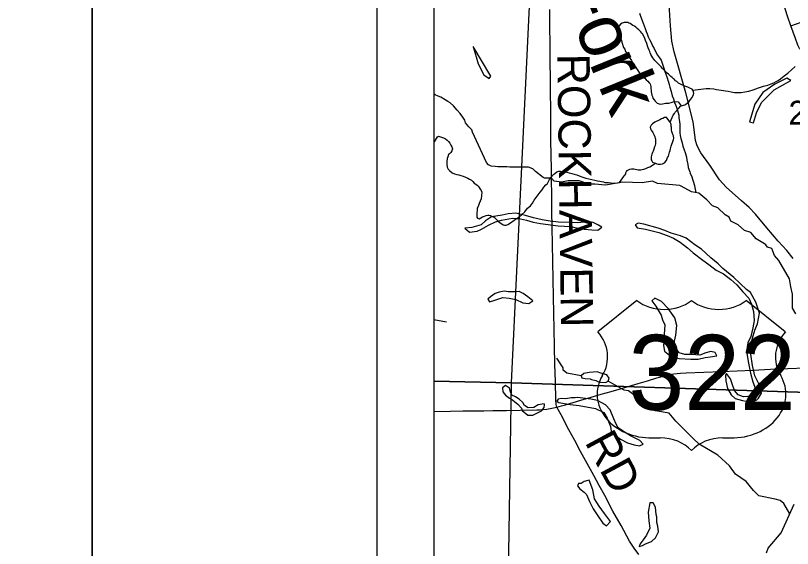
# Model space of a CAD drawing. Extents: x -6.1 to 38, y -7.7 to 22.
# Drawn here: x 1.365 to 2.73, y 15.778 to 16.715 of the extents above; entities that cross this region are included whole.
import ezdxf

# ---------------------------------------------------------------- set-up
doc = ezdxf.new("R2010")
doc.units = 0
for name, color, linetype in [('GM_X_Corporation', 7, 'Continuous'), ('GM_X_Minor_Lake', 7, 'Continuous'), ('GM_X_Minor_River', 7, 'Continuous'), ('GM_X_Minor_River_Text', 7, 'Continuous'), ('GM_X_Section_Text', 7, 'Continuous'), ('GM_X_Township_Road', 7, 'Continuous'), ('GM_X_Township_Road_Text', 7, 'Continuous'), ('GM_X_US_Location', 7, 'Continuous'), ('GM_X_US_Route', 7, 'Continuous'), ('GM_X_US_Shield', 7, 'Continuous'), ('SH_Border', 7, 'Continuous'), ('SH_Data', 7, 'Continuous')]:
    doc.layers.add(name, color=color, linetype=linetype)

msp = doc.modelspace()

# ---------------------------------------------------------------- linework, layer by layer
at = {"layer": 'GM_X_Corporation'}
for points in [[(2.1, 20.0941), (2.1, 15.0637), (2.2727, 15.0594), (2.8416, 15.0475)], [(2.1, 19.3655), (2.1, 14.5232), (2.6997, 14.5255), (2.9953, 14.5306)]]:
    msp.add_lwpolyline(points, dxfattribs=at)
for points in [[(2.1, 17.0798), (2.1, 16.0722), (2.2364, 16.0695), (2.2848, 17.0751)], [(2.2848, 17.0751), (3.2573, 17.0475), (3.2572, 17.0301), (3.2483, 16.4521), (3.2427, 16.0367), (2.2364, 16.0695)], [(2.1, 16.0722), (2.1, 15.064), (2.1873, 15.0619), (2.2211, 15.061), (2.2364, 16.0695)], [(2.2364, 16.0695), (3.2427, 16.0367), (3.2407, 15.9466), (3.2349, 15.609), (3.2294, 15.3062), (3.225, 15.0392), (2.2211, 15.061)]]:
    msp.add_lwpolyline(points, close=True, dxfattribs=at)
at = {"layer": 'GM_X_Minor_Lake'}
for p, q in [((2.3801, 16.3513), (2.3643, 16.3518)), ((2.4943, 16.3415), (2.4694, 16.3484)), ((2.2452, 16.2293), (2.235, 16.2293)), ((2.4902, 16.2039), (2.4962, 16.1944)), ((2.3774, 16.075), (2.3849, 16.0733)), ((2.3759, 16.0404), (2.3528, 16.0435)), ((2.2424, 16.0359), (2.2477, 16.0321)), ((2.3642, 15.896), (2.3592, 15.8926)), ((2.4921, 15.8237), (2.4918, 15.8337))]:
    msp.add_line(p, q, dxfattribs=at)
for points in [[(2.5126, 16.6118), (2.5103, 16.6141), (2.5076, 16.6163), (2.5049, 16.619), (2.5018, 16.6223), (2.4999, 16.625), (2.4968, 16.628), (2.4949, 16.6299), (2.4888, 16.6363), (2.4868, 16.6385), (2.4849, 16.6408), (2.483, 16.6438), (2.4818, 16.6469), (2.4806, 16.6495), (2.4798, 16.6518), (2.4783, 16.6544), (2.4771, 16.6582), (2.4759, 16.6616), (2.4743, 16.6662), (2.4724, 16.6711), (2.4708, 16.6756), (2.4689, 16.6794), (2.4673, 16.6821), (2.4658, 16.6843), (2.4642, 16.6862), (2.4623, 16.6881), (2.4604, 16.69), (2.4573, 16.6922), (2.455, 16.6945), (2.4527, 16.6964), (2.45, 16.6979), (2.4477, 16.6994), (2.4454, 16.7009), (2.4431, 16.702), (2.4412, 16.7027), (2.4393, 16.7031), (2.4367, 16.7031), (2.4348, 16.703), (2.4314, 16.7019), (2.4283, 16.6999), (2.4261, 16.6973), (2.425, 16.6953), (2.425, 16.6923), (2.425, 16.6896), (2.4258, 16.6855), (2.4263, 16.6828), (2.427, 16.6805), (2.4274, 16.6783), (2.4282, 16.676), (2.429, 16.6741), (2.4298, 16.6711), (2.4306, 16.6684), (2.4337, 16.6589), (2.4357, 16.6559), (2.4369, 16.6521), (2.4388, 16.6495), (2.4407, 16.6461), (2.4427, 16.643), (2.4446, 16.6404), (2.4462, 16.6378), (2.4473, 16.6359), (2.4485, 16.6332), (2.4497, 16.6313), (2.4508, 16.6294), (2.4524, 16.6276), (2.4551, 16.6238), (2.4574, 16.62), (2.4597, 16.6166), (2.4616, 16.6136), (2.4632, 16.6113), (2.4655, 16.6094), (2.4682, 16.6076), (2.4709, 16.6049), (2.4736, 16.6023), (2.4763, 16.5997), (2.4786, 16.597), (2.4801, 16.5948), (2.4813, 16.5906), (2.4813, 16.5887), (2.4817, 16.586), (2.4821, 16.5837), (2.4822, 16.5811), (2.4826, 16.578), (2.483, 16.5754), (2.4842, 16.5727), (2.4853, 16.5701), (2.4873, 16.5667), (2.4892, 16.5644), (2.4927, 16.561), (2.4961, 16.5599), (2.4984, 16.5596), (2.5018, 16.56), (2.5048, 16.5604), (2.5075, 16.5608), (2.5094, 16.5608), (2.5132, 16.5612), (2.517, 16.562), (2.5208, 16.5632), (2.5268, 16.564), (2.5295, 16.5633), (2.5349, 16.5561)], [(2.1691, 16.6607), (2.1784, 16.6304), (2.1883, 16.6111), (2.1977, 16.6047), (2.2004, 16.6085)], [(2.2004, 16.6085), (2.1691, 16.6607)], [(2.5349, 16.5561), (2.5414, 16.5581), (2.5432, 16.5593), (2.5451, 16.5612), (2.5481, 16.5635), (2.5515, 16.5673), (2.5541, 16.5712), (2.5556, 16.5738), (2.5567, 16.5757), (2.5571, 16.578), (2.5567, 16.5811), (2.5555, 16.5837), (2.554, 16.5856), (2.5513, 16.5871), (2.549, 16.5882), (2.5467, 16.589), (2.5448, 16.5897), (2.5429, 16.5904), (2.541, 16.5912), (2.5391, 16.5919), (2.5372, 16.5927), (2.5337, 16.5945), (2.5303, 16.5964), (2.5272, 16.599), (2.5249, 16.6001), (2.523, 16.6024), (2.5211, 16.6039), (2.5191, 16.6062), (2.5168, 16.608), (2.5149, 16.6099), (2.5126, 16.6118)], [(2.7206, 16.6053), (2.6992, 16.5943), (2.6781, 16.5798), (2.6642, 16.5596), (2.6549, 16.5285), (2.6621, 16.5267)], [(2.6621, 16.5267), (2.6669, 16.5441), (2.6759, 16.5623), (2.6981, 16.5844), (2.7278, 16.6012), (2.7206, 16.6053)], [(2.5097, 16.5357), (2.5055, 16.5357), (2.5025, 16.5341), (2.5002, 16.5334), (2.4976, 16.5318), (2.4949, 16.5303), (2.4911, 16.5287), (2.4885, 16.5275), (2.4843, 16.5248), (2.4821, 16.5225), (2.4806, 16.5187), (2.481, 16.5157), (2.4822, 16.5134), (2.4837, 16.5115), (2.4849, 16.5093), (2.4861, 16.5074), (2.4876, 16.5047), (2.4888, 16.5021), (2.4892, 16.4998), (2.49, 16.4979), (2.49, 16.4956), (2.49, 16.493), (2.4897, 16.4899), (2.489, 16.4869), (2.4879, 16.4842), (2.4868, 16.4804), (2.4857, 16.4766), (2.4842, 16.4743), (2.4831, 16.4712), (2.4827, 16.4689), (2.482, 16.4666), (2.482, 16.4632), (2.482, 16.4613), (2.4832, 16.4594), (2.4844, 16.4575), (2.4874, 16.4561), (2.4897, 16.4553), (2.492, 16.4542), (2.4943, 16.4538), (2.4966, 16.4539), (2.4985, 16.4539), (2.5019, 16.4543), (2.5053, 16.4562), (2.509, 16.4604), (2.5109, 16.4654), (2.5124, 16.4681), (2.5138, 16.4723), (2.5146, 16.475), (2.5153, 16.4776), (2.516, 16.4807), (2.5168, 16.4833), (2.5175, 16.4852), (2.5186, 16.4887), (2.5193, 16.4917), (2.5208, 16.4952), (2.5215, 16.4971), (2.5219, 16.4997), (2.5211, 16.5035), (2.5203, 16.5058), (2.5191, 16.5092), (2.5183, 16.5115), (2.5179, 16.5138), (2.5179, 16.5164), (2.5179, 16.5183), (2.5175, 16.5202), (2.5171, 16.5236), (2.5166, 16.5255), (2.5155, 16.5274), (2.5099, 16.5354)], [(2.5099, 16.5354), (2.5097, 16.5357)], [(2.3643, 16.3518), (2.3533, 16.3507), (2.3378, 16.3515), (2.3193, 16.3519), (2.3049, 16.3535), (2.2905, 16.3562), (2.2754, 16.3593), (2.2614, 16.3638), (2.2444, 16.3677), (2.2308, 16.3662), (2.2202, 16.364), (2.2013, 16.361), (2.1911, 16.3542), (2.1831, 16.3474), (2.1669, 16.3425), (2.1544, 16.3414), (2.1631, 16.3342), (2.1763, 16.336), (2.1839, 16.3394), (2.196, 16.3466), (2.2085, 16.3526), (2.2191, 16.3556), (2.2387, 16.3586), (2.2527, 16.3578), (2.2629, 16.3551), (2.275, 16.3517), (2.2875, 16.3494), (2.3185, 16.3451), (2.3412, 16.3443), (2.3582, 16.34), (2.3778, 16.3385), (2.3881, 16.3377), (2.3952, 16.343), (2.3896, 16.3468), (2.3801, 16.3513)], [(2.4694, 16.3484), (2.4592, 16.35), (2.4542, 16.3473), (2.4573, 16.342), (2.4724, 16.3397), (2.4954, 16.3339), (2.5102, 16.3282), (2.5211, 16.3236), (2.5328, 16.3168), (2.546, 16.3069), (2.5558, 16.2981), (2.5728, 16.2852), (2.5834, 16.2772), (2.5966, 16.2676), (2.6094, 16.2612), (2.6219, 16.2509), (2.6324, 16.2414), (2.6434, 16.2296), (2.6536, 16.2182), (2.6584, 16.2075), (2.6622, 16.1946), (2.6633, 16.1787), (2.661, 16.1658), (2.6572, 16.1507), (2.6522, 16.1397), (2.6495, 16.1245), (2.6529, 16.1037), (2.6566, 16.0866), (2.6607, 16.0714), (2.6652, 16.0589), (2.6644, 16.0498), (2.6595, 16.046), (2.6444, 16.0445), (2.6349, 16.0484), (2.6285, 16.0556), (2.6244, 16.0674), (2.6214, 16.0765), (2.6143, 16.086), (2.6127, 16.0829), (2.6131, 16.0731), (2.6161, 16.0594), (2.6225, 16.048), (2.6296, 16.0419), (2.6425, 16.0381), (2.6493, 16.037), (2.6606, 16.0362), (2.6678, 16.0395), (2.6705, 16.0422), (2.6762, 16.0513), (2.6743, 16.0615), (2.6645, 16.0816), (2.66, 16.0999), (2.6571, 16.12), (2.6575, 16.1344), (2.6602, 16.1476), (2.664, 16.162), (2.6689, 16.173), (2.6724, 16.192), (2.666, 16.2113), (2.6566, 16.2284), (2.6494, 16.2334), (2.6272, 16.2547), (2.6083, 16.2706), (2.6, 16.2786), (2.5868, 16.2893), (2.5706, 16.3041), (2.5589, 16.3121), (2.5438, 16.3235), (2.5336, 16.3281), (2.517, 16.3323), (2.506, 16.3369), (2.4943, 16.3415)], [(2.235, 16.2293), (2.2308, 16.2293), (2.224, 16.2305), (2.2153, 16.2286), (2.2078, 16.2264), (2.1998, 16.2207), (2.1949, 16.2162), (2.1983, 16.212), (2.2074, 16.2146), (2.2214, 16.2191), (2.2323, 16.2183), (2.2444, 16.2156), (2.2565, 16.2103), (2.2671, 16.2087), (2.2739, 16.2137), (2.2656, 16.2205), (2.2569, 16.2262), (2.2501, 16.2297), (2.2452, 16.2293)], [(2.4962, 16.1944), (2.4996, 16.1883), (2.5022, 16.1803), (2.506, 16.1712), (2.5052, 16.1542), (2.5051, 16.1447), (2.5036, 16.1348), (2.5058, 16.125), (2.5175, 16.1158), (2.5311, 16.1124), (2.5516, 16.1108), (2.5648, 16.1108), (2.5769, 16.1138), (2.5856, 16.1149), (2.5973, 16.1167), (2.5943, 16.1228), (2.5871, 16.1243), (2.5781, 16.1221), (2.5678, 16.118), (2.5538, 16.1191), (2.5414, 16.1192), (2.5312, 16.1219), (2.5244, 16.1321), (2.5229, 16.1427), (2.5256, 16.153), (2.5271, 16.17), (2.5234, 16.1837), (2.5117, 16.2), (2.5, 16.2122), (2.4887, 16.2183), (2.483, 16.2138), (2.4902, 16.2039)], [(2.3849, 16.0733), (2.3881, 16.0719), (2.393, 16.0703), (2.4017, 16.0699), (2.4066, 16.0722), (2.4081, 16.0775), (2.4044, 16.0836), (2.3938, 16.0866), (2.3874, 16.0889), (2.3734, 16.0875), (2.3639, 16.0856), (2.359, 16.0818), (2.3605, 16.0784), (2.3662, 16.0772), (2.3749, 16.0761), (2.3774, 16.075)], [(2.2477, 16.0321), (2.2541, 16.0249), (2.2552, 16.0207), (2.2654, 16.0127), (2.2741, 16.0127), (2.2813, 16.0161), (2.2893, 16.0202), (2.2942, 16.0259), (2.2946, 16.0305), (2.2942, 16.0327), (2.2836, 16.0309), (2.2757, 16.026), (2.2662, 16.0256), (2.2598, 16.0294), (2.2564, 16.0347), (2.25, 16.0408), (2.2436, 16.0446), (2.2375, 16.0477), (2.2349, 16.0538), (2.2334, 16.0598), (2.2262, 16.0648), (2.2209, 16.0606), (2.2213, 16.0534), (2.2262, 16.0477), (2.2334, 16.0424), (2.2383, 16.0397), (2.2424, 16.0359)], [(2.3528, 16.0435), (2.3483, 16.0432), (2.3415, 16.0432), (2.332, 16.041), (2.3241, 16.0417), (2.3184, 16.0406), (2.3162, 16.0372), (2.3196, 16.0345), (2.3396, 16.0315), (2.3555, 16.0295), (2.3842, 16.0245), (2.3989, 16.0169), (2.4049, 16.0074), (2.4109, 15.9926), (2.4117, 15.9846), (2.417, 15.9785), (2.4283, 15.9701), (2.4407, 15.9637), (2.4521, 15.9602), (2.4615, 15.9583), (2.468, 15.9617), (2.4623, 15.9681), (2.4457, 15.9761), (2.4366, 15.9819), (2.4242, 15.9902), (2.4208, 15.9967), (2.4163, 16.0058), (2.4099, 16.0218), (2.402, 16.0309), (2.388, 16.0381), (2.3759, 16.0404)], [(2.3592, 15.8926), (2.3543, 15.8926), (2.3524, 15.8885), (2.357, 15.8828), (2.3641, 15.8774), (2.3687, 15.8733), (2.3739, 15.8607), (2.3803, 15.8478), (2.3882, 15.8357), (2.3969, 15.8227), (2.4037, 15.8182), (2.4109, 15.8257), (2.3999, 15.8398), (2.3909, 15.8527), (2.3826, 15.8652), (2.3796, 15.8812), (2.3729, 15.8983), (2.3706, 15.8979), (2.3642, 15.896)], [(2.4918, 15.8337), (2.4911, 15.8376), (2.49, 15.8505), (2.4855, 15.8581), (2.4798, 15.8585), (2.4767, 15.8422), (2.4778, 15.8267), (2.4797, 15.8138), (2.474, 15.8016), (2.4679, 15.7933), (2.4626, 15.7861), (2.461, 15.7816), (2.4667, 15.7831), (2.4724, 15.7861), (2.4826, 15.7902), (2.4898, 15.797), (2.4948, 15.8073), (2.494, 15.8171), (2.4921, 15.8237)]]:
    msp.add_lwpolyline(points, dxfattribs=at)
at = {"layer": 'GM_X_Minor_River'}
for points in [[(2.4617, 16.7191), (2.4636, 16.7138), (2.4663, 16.7066), (2.4682, 16.7017), (2.4697, 16.6968), (2.4716, 16.6922), (2.4731, 16.6869), (2.4751, 16.6828), (2.477, 16.6775), (2.4793, 16.6729), (2.4819, 16.668), (2.4846, 16.662), (2.4873, 16.6571), (2.4911, 16.6495), (2.493, 16.6453), (2.4968, 16.6408), (2.4998, 16.6366), (2.5029, 16.626), (2.5052, 16.6207), (2.506, 16.6166), (2.5098, 16.6071), (2.5125, 16.598), (2.514, 16.5939), (2.5148, 16.5893), (2.5171, 16.5818), (2.519, 16.5742), (2.5213, 16.5685), (2.5232, 16.5625), (2.5255, 16.5572), (2.5271, 16.5522), (2.5305, 16.5397), (2.5309, 16.5356), (2.5321, 16.5284), (2.5325, 16.5242), (2.5325, 16.517), (2.5322, 16.5132), (2.5326, 16.5087), (2.5333, 16.5041), (2.5345, 16.4992), (2.5368, 16.4913), (2.538, 16.4852), (2.5399, 16.4792), (2.5418, 16.4742), (2.5433, 16.4701), (2.5441, 16.4659), (2.5449, 16.461), (2.5464, 16.453), (2.5472, 16.4481), (2.5499, 16.4405), (2.5507, 16.4377)], [(2.5555, 16.5837), (2.579, 16.5866), (2.5851, 16.5867), (2.5924, 16.586), (2.5969, 16.5849), (2.6011, 16.5846), (2.6053, 16.5842), (2.6091, 16.5835), (2.6129, 16.5828), (2.6175, 16.5821), (2.6228, 16.581), (2.6285, 16.5799), (2.64, 16.5796), (2.6464, 16.5808), (2.6536, 16.5824), (2.6616, 16.5848), (2.6706, 16.5879), (2.6797, 16.591), (2.6873, 16.593), (2.693, 16.595), (2.6975, 16.5969), (2.7017, 16.5989), (2.7055, 16.6008), (2.7096, 16.6039), (2.716, 16.6089), (2.722, 16.6139), (2.7284, 16.6197), (2.7352, 16.6254)], [(2.279, 16.4411), (2.2741, 16.4455), (2.2665, 16.4485), (2.251, 16.4484), (2.2469, 16.4488), (2.2404, 16.4484), (2.234, 16.4487), (2.2283, 16.4491), (2.2231, 16.4494), (2.2125, 16.4494), (2.2079, 16.4497), (2.2011, 16.4505), (2.1962, 16.4524), (2.1928, 16.4569), (2.168, 16.5102), (2.1668, 16.5144), (2.1619, 16.5193), (2.1558, 16.5265), (2.1547, 16.531), (2.1512, 16.5367), (2.1467, 16.5427), (2.141, 16.5488), (2.1349, 16.5563), (2.1288, 16.5616), (2.125, 16.5639), (2.1201, 16.5669), (2.1125, 16.5714), (2.1076, 16.5733), (2.1027, 16.5759), (2.1, 16.5772)], [(2.5155, 16.5274), (2.521, 16.54), (2.5229, 16.5427), (2.5244, 16.545), (2.5289, 16.5504), (2.5312, 16.5531), (2.5338, 16.5557), (2.5349, 16.5561)], [(2.1, 16.4932), (2.1011, 16.4929), (2.1064, 16.5017), (2.1086, 16.5028), (2.1121, 16.5021), (2.1174, 16.5003), (2.1208, 16.4984)], [(2.1208, 16.4984), (2.1239, 16.4962), (2.1262, 16.4935), (2.1285, 16.4905), (2.1301, 16.4871), (2.1316, 16.4844), (2.1324, 16.4826), (2.1328, 16.4807), (2.1321, 16.4772), (2.1299, 16.4742), (2.128, 16.4722), (2.1261, 16.4707), (2.1246, 16.4669), (2.1235, 16.4635), (2.1228, 16.4585), (2.1229, 16.4536), (2.1237, 16.4486), (2.1253, 16.4452), (2.128, 16.4426), (2.1326, 16.4388), (2.1368, 16.437), (2.1406, 16.4359), (2.1444, 16.4348), (2.1478, 16.4337), (2.1516, 16.4326), (2.1558, 16.4307), (2.1597, 16.4292), (2.1631, 16.4273), (2.1662, 16.4255), (2.1689, 16.4232), (2.1712, 16.4206), (2.1742, 16.4187), (2.1762, 16.4168), (2.1781, 16.415), (2.18, 16.4127), (2.1819, 16.41), (2.1835, 16.4074), (2.1847, 16.4048), (2.1833, 16.3926), (2.1818, 16.3888), (2.1799, 16.3846), (2.1788, 16.3811), (2.1774, 16.3784), (2.1766, 16.3762), (2.1763, 16.3731), (2.1756, 16.3685), (2.1756, 16.364), (2.176, 16.3606), (2.1772, 16.3587), (2.1799, 16.3576), (2.1855, 16.361), (2.1893, 16.3626), (2.1924, 16.3638), (2.195, 16.3642), (2.1973, 16.3642), (2.1996, 16.3635), (2.2026, 16.362), (2.2061, 16.3605), (2.2088, 16.3582), (2.2111, 16.356), (2.2134, 16.3537), (2.2168, 16.3507), (2.2195, 16.3488), (2.2222, 16.3473), (2.2245, 16.3466), (2.2271, 16.3466), (2.2302, 16.3478), (2.2351, 16.3509), (2.2415, 16.3551), (2.2483, 16.3598), (2.2543, 16.3648), (2.2599, 16.3698), (2.2648, 16.3763), (2.2701, 16.3805), (2.2735, 16.3855), (2.2768, 16.3905), (2.2798, 16.3951), (2.2836, 16.3997), (2.2873, 16.4043), (2.2903, 16.4085), (2.2937, 16.4131), (2.297, 16.4173), (2.2997, 16.4196), (2.3012, 16.4219), (2.3034, 16.4268), (2.306, 16.4303), (2.3113, 16.436), (2.3131, 16.4376), (2.3165, 16.4403), (2.3196, 16.4415), (2.3226, 16.4415), (2.326, 16.4411), (2.3298, 16.4404), (2.334, 16.4397), (2.3382, 16.4386), (2.3428, 16.4375), (2.347, 16.436), (2.3516, 16.4349), (2.3558, 16.4331), (2.3619, 16.4312), (2.3672, 16.4294)], [(2.3672, 16.4294), (2.3726, 16.4279), (2.3779, 16.4268), (2.3832, 16.4257), (2.3878, 16.4246), (2.392, 16.4239), (2.395, 16.4232), (2.3981, 16.4225), (2.4004, 16.4217), (2.4023, 16.4217), (2.4042, 16.4214), (2.4072, 16.4214), (2.411, 16.4211), (2.4152, 16.4207), (2.419, 16.4204), (2.4232, 16.4208), (2.4262, 16.4216), (2.4296, 16.4258), (2.4322, 16.4296), (2.4345, 16.4331), (2.4363, 16.435), (2.4375, 16.4369), (2.4378, 16.4388), (2.4389, 16.4407), (2.4401, 16.4427), (2.4423, 16.4438), (2.4446, 16.445), (2.4476, 16.4454), (2.4514, 16.4454), (2.4594, 16.444), (2.4613, 16.444), (2.464, 16.444), (2.4663, 16.4444), (2.4693, 16.4452), (2.4727, 16.4464), (2.4765, 16.448), (2.4799, 16.4491), (2.4897, 16.4553)], [(2.6459, 16.3369), (2.635, 16.3472), (2.6222, 16.3536), (2.6192, 16.3605), (2.6124, 16.365), (2.5995, 16.3772), (2.5897, 16.3803), (2.5799, 16.3909), (2.5659, 16.4027), (2.5531, 16.4054), (2.535, 16.4153), (2.5327, 16.4165), (2.4934, 16.42), (2.4847, 16.4238), (2.4662, 16.4208), (2.4321, 16.4221), (2.4019, 16.4169), (2.383, 16.4184), (2.3724, 16.4185), (2.3558, 16.4246), (2.3365, 16.4247), (2.3244, 16.4224), (2.3119, 16.424), (2.307, 16.4293), (2.2945, 16.429), (2.2923, 16.4301), (2.279, 16.4411)], [(2.561, 16.4038), (2.5588, 16.416), (2.5533, 16.433), (2.5507, 16.4377)], [(2.7363, 16.1906), (2.7303, 16.2005), (2.7307, 16.2252), (2.7273, 16.2381), (2.7251, 16.2521), (2.7067, 16.2844), (2.6988, 16.2935), (2.6943, 16.3053), (2.6863, 16.3079), (2.6833, 16.3121), (2.6814, 16.314), (2.6667, 16.3228), (2.6573, 16.3334), (2.6459, 16.3369)], [(2.359, 16.0818), (2.3341, 16.0861), (2.3273, 16.0918), (2.3273, 16.0959), (2.3164, 16.113)], [(2.7255, 15.8393), (2.7154, 15.857), (2.7089, 15.8624), (2.6999, 15.8647), (2.6712, 15.8704), (2.6621, 15.8799), (2.6493, 15.8959), (2.6304, 15.9085), (2.6199, 15.9233), (2.5991, 15.9423), (2.5667, 15.9614), (2.5557, 15.9716), (2.5255, 16.0021), (2.5135, 16.0161), (2.49, 16.0204), (2.487, 16.0215), (2.4742, 16.0254), (2.4538, 16.0463), (2.4425, 16.0554), (2.4346, 16.0566), (2.4191, 16.065), (2.4066, 16.0722)], [(2.6845, 15.7707), (2.6875, 15.7786), (2.7103, 15.8055), (2.7331, 15.8562)]]:
    msp.add_lwpolyline(points, dxfattribs=at)
at = {"layer": 'GM_X_Township_Road'}
msp.add_line((2.1, 16.1805), (2.1226, 16.1768), dxfattribs=at)
for points in [[(2.7521, 16.6497), (2.7474, 16.6527), (2.7429, 16.6571), (2.7398, 16.6631), (2.7355, 16.6749), (2.7278, 16.6972), (2.7225, 16.7121), (2.7173, 16.727), (2.7121, 16.7422), (2.7068, 16.7573), (2.7036, 16.7679), (2.7025, 16.776), (2.702, 16.7801), (2.7019, 16.7897), (2.7016, 16.8119), (2.7013, 16.8342), (2.701, 16.8653), (2.7007, 16.891), (2.7004, 16.9167), (2.7001, 16.9444), (2.6997, 16.9721), (2.6997, 16.9822)], [(2.4604, 15.7675), (2.4525, 15.7789), (2.4442, 15.7912), (2.4294, 15.8184), (2.4147, 15.844), (2.4004, 15.871), (2.3908, 15.8886), (2.3812, 15.9063), (2.3697, 15.9274), (2.3582, 15.9485), (2.3478, 15.9677), (2.3374, 15.9869), (2.3238, 16.013), (2.3164, 16.0265), (2.3154, 16.031), (2.3145, 16.04), (2.3138, 16.071), (2.3131, 16.1021), (2.3124, 16.133), (2.3117, 16.1639), (2.3111, 16.1921), (2.3105, 16.2203), (2.3099, 16.2513), (2.3093, 16.2824), (2.3087, 16.3134), (2.3081, 16.3422), (2.3075, 16.3709), (2.3073, 16.402), (2.3071, 16.4236), (2.3069, 16.4451), (2.3065, 16.4704), (2.306, 16.4956), (2.3059, 16.524), (2.3058, 16.5523), (2.3055, 16.5778), (2.3051, 16.6033), (2.3048, 16.6343), (2.3046, 16.6654), (2.3043, 16.6956), (2.3041, 16.7258)], [(2.7318, 16.288), (2.7202, 16.3023), (2.7052, 16.3183), (2.6856, 16.3416), (2.6653, 16.366), (2.6543, 16.3774), (2.641, 16.3893), (2.6139, 16.4136), (2.6024, 16.4265), (2.5853, 16.4523), (2.5693, 16.474), (2.5628, 16.4861), (2.5601, 16.4955), (2.5579, 16.5145), (2.5558, 16.5284), (2.5431, 16.5792), (2.5223, 16.6516), (2.5182, 16.67), (2.5161, 16.6973), (2.5139, 16.7347)], [(2.7278, 16.6972), (2.7571, 16.7075)]]:
    msp.add_lwpolyline(points, dxfattribs=at)
at = {"layer": 'GM_X_US_Route'}
msp.add_lwpolyline([(2.1, 16.019), (2.1295, 16.0196), (2.1509, 16.02), (2.1722, 16.0203), (2.1881, 16.0204), (2.2041, 16.0205), (2.2281, 16.0209), (2.2521, 16.0213), (2.2813, 16.0218), (2.286, 16.022), (2.2985, 16.023), (2.3164, 16.0265), (2.3245, 16.0289), (2.3313, 16.0309), (2.3584, 16.0387), (2.3764, 16.0439), (2.3944, 16.0492), (2.4121, 16.0542), (2.4297, 16.0592), (2.4595, 16.0682), (2.4758, 16.0731), (2.4921, 16.078), (2.504, 16.0813), (2.5119, 16.0833), (2.5176, 16.0845), (2.522, 16.0851), (2.5275, 16.0857), (2.5337, 16.0863), (2.5437, 16.0868), (2.5747, 16.0881), (2.6058, 16.0895), (2.6333, 16.0907), (2.6608, 16.0919), (2.6918, 16.0932), (2.7225, 16.0944), (2.7532, 16.0956)], dxfattribs=at)
at = {"layer": 'GM_X_US_Shield'}
for p, q in [((2.4569, 16.2141), (2.3882, 16.1591)), ((2.7178, 16.1591), (2.6491, 16.2141)), ((2.4844, 15.9724), (2.4981, 15.9724)), ((2.608, 15.9724), (2.6217, 15.9724))]:
    msp.add_line(p, q, dxfattribs=at)
for centre, major_axis, start_param, end_param in [((2.505, 16.2533), (-0.0687, 0), 0.795399, 2.346194), ((2.6011, 16.2533), (-0.0687, 0), 0.795399, 2.346194), ((2.3095, 16.115), (0.0961, 0), 5.838949, 6.894067), ((2.7966, 16.115), (-0.0961, 0), 5.672304, 6.727422), ((2.4833, 16.0493), (0.0961, 0), 2.702327, 4.723529), ((2.6228, 16.0493), (-0.0961, 0), 1.559657, 3.580859), ((2.4981, 15.9174), (-0.0687, 0), 3.785094, 4.712389), ((2.608, 15.9174), (-0.0687, 0), 4.712389, 5.639684)]:
    msp.add_ellipse(centre, major_axis=major_axis, ratio=0.8, start_param=start_param, end_param=end_param, dxfattribs=at)
at = {"layer": 'SH_Border'}
for points in [[(0.5, 21.5), (1.5, 21.5), (1.5, 0.5), (0.5, 0.5)], [(1.5, 21.5), (33.5, 21.5), (33.5, 0.5), (1.5, 0.5)]]:
    msp.add_lwpolyline(points, close=True, dxfattribs=at)
at = {"layer": 'SH_Data'}
for p, q in [((2, 21), (2, 14)), ((2.1, 20.9), (2.1, 14.1))]:
    msp.add_line(p, q, dxfattribs=at)

# ---------------------------------------------------------------- texts
at = {"layer": 'GM_X_Minor_River_Text'}
msp.add_text('Fork', height=0.0947, rotation=292.189, dxfattribs=at).set_placement((2.3169, 16.7689))
at = {"layer": 'GM_X_Section_Text'}
msp.add_text('20', height=0.04186, rotation=0, dxfattribs=at).set_placement((2.7234, 16.5235))
at = {"layer": 'GM_X_Township_Road_Text'}
for s, rotation, p in [('ROCKHAVEN', 270.7666, (2.3172, 16.6477)), ('RD', 298.335, (2.3645, 15.9654))]:
    msp.add_text(s, height=0.05682, rotation=rotation, dxfattribs=at).set_placement(p)
at = {"layer": 'GM_X_US_Location'}
for s in ['0', '/']:
    msp.add_text(s, height=0.000189, dxfattribs=at).set_placement((2.5531, 16.0876))
msp.add_text('322', height=0.000189, rotation=0, dxfattribs=at).set_placement((2.4949, 16.0484))
at = {"layer": 'GM_X_US_Shield'}
msp.add_text('322', height=0.13184, dxfattribs=at).set_placement((2.4422, 16.0218))

doc.saveas('drawing.dxf')
